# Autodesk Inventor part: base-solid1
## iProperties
Shininess: 64.0
Length Units: 11272
Angle Units: 11279
Time Units: 11290
Mass Units: 11286
Length Display Precision: 3
Angle Display Precision: 2
Compacted: True
Part Number: base-solid1
Document SubType Name: Modeling
Created: 2002-11
Designer: Elise Moss
Density: 0.0
Volumn: 0.0
Area: 0.0
PropertySet Name: Model Information
Control State: 0
Master: False
Checked Out: False
Author: Elise Moss
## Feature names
1. Base1
